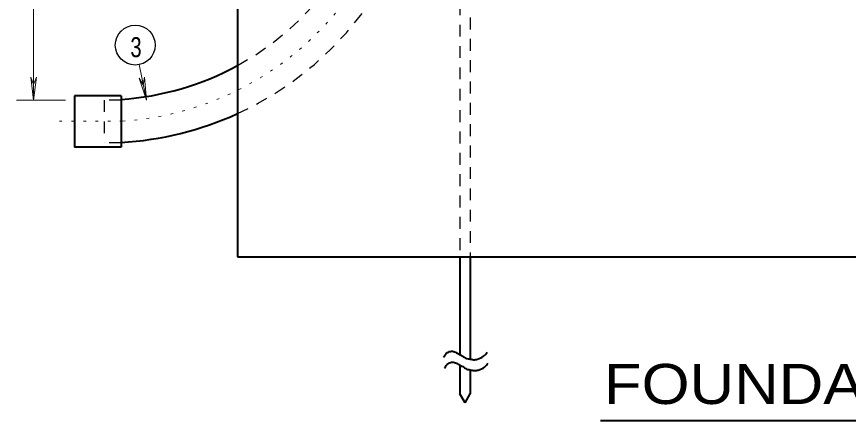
# Model space of a CAD drawing. Extents: x 312583 to 312854, y 144419 to 144597.
# Drawn here: x 312769.66 to 312801.16, y 144515.02 to 144530.33 of the extents above; entities that cross this region are included whole.
import ezdxf
from ezdxf.enums import TextEntityAlignment as Align

# ---------------------------------------------------------------- set-up
doc = ezdxf.new("R2010")
doc.units = 0
doc.header["$LTSCALE"] = 0.3
doc.linetypes.add('DOTTED', pattern=[1.5, 0.3, -1.2])
doc.linetypes.add('SHORT_DASHED', pattern=[2.7, 1.5, -1.2])
doc.layers.add('1', color=7, linetype='Continuous', lineweight=25)
doc.layers.add('2', color=7, linetype='Continuous', lineweight=13)

msp = doc.modelspace()

# ---------------------------------------------------------------- linework, layer by layer
at = {"layer": '1', "lineweight": 40}
for p, q in [((312778.0166, 144543.5879), (312778.0166, 144521.2243)), ((312773.616, 144527.3269), (312771.8526, 144527.3269)), ((312771.8526, 144527.3269), (312771.8526, 144525.3796)), ((312773.616, 144527.3269), (312773.616, 144525.3796)), ((312773.616, 144525.3796), (312771.8526, 144525.3796)), ((312778.0166, 144521.2243), (312840.6303, 144521.2243)), ((312786.4423, 144521.2243), (312786.4423, 144517.5136)), ((312786.841, 144521.2243), (312786.841, 144517.3449)), ((312786.4423, 144517.1149), (312786.4423, 144516.0263)), ((312786.841, 144516.9386), (312786.841, 144516.0263)), ((312786.6416, 144515.6813), (312786.4423, 144516.0263)), ((312786.6416, 144515.6813), (312786.841, 144516.0263))]:
    msp.add_line(p, q, dxfattribs=at)
at = {"layer": '1', "linetype": 'SHORT_DASHED'}
for p, q in [((312786.4423, 144534.0736), (312786.4423, 144521.2243)), ((312786.841, 144533.5369), (312786.841, 144521.2243)), ((312772.972, 144527.1659), (312772.972, 144525.5406)), ((312773.616, 144527.1659), (312772.972, 144527.1659)), ((312773.616, 144525.5406), (312772.972, 144525.5406))]:
    msp.add_line(p, q, dxfattribs=at)
at = {"layer": '1', "linetype": 'DOTTED', "lineweight": 13}
msp.add_line((312773.6696, 144526.3609), (312771.2776, 144526.3609), dxfattribs=at)
at = {"layer": '1', "linetype": 'SHORT_DASHED'}
for radius, start, end in [(10.6854, 298.57546, 1.79804), (12.3146, 294.52268, 358.54105)]:
    msp.add_arc((312772.9074, 144537.8539), radius, start, end, dxfattribs=at)
at = {"layer": '1', "linetype": 'DOTTED', "lineweight": 13}
msp.add_arc((312772.9074, 144537.8539), 11.516, 273.78468, 358.54081, dxfattribs=at)
at = {"layer": '1', "lineweight": 40}
for radius, start, end in [(10.6854, 273.78479, 298.57546), (12.3146, 273.28349, 294.52268)]:
    msp.add_arc((312772.9074, 144537.8539), radius, start, end, dxfattribs=at)
for points in [[(312785.829, 144517.4139), (312785.9746, 144517.5903), (312786.128, 144517.6439), (312786.2813, 144517.6056), (312786.4116, 144517.5289), (312786.5573, 144517.4523), (312786.6723, 144517.3833), (312786.841, 144517.3449), (312786.9713, 144517.3219), (312787.1093, 144517.3449), (312787.347, 144517.4523), (312787.485, 144517.6056)], [(312785.8673, 144517.0076), (312786.013, 144517.1763), (312786.1663, 144517.2299), (312786.3196, 144517.1916), (312786.45, 144517.1149), (312786.5956, 144517.0383), (312786.7106, 144516.9693), (312786.8793, 144516.9309), (312787.0096, 144516.9079), (312787.14, 144516.9309), (312787.3853, 144517.0383), (312787.5156, 144517.1916)]]:
    msp.add_spline(points, degree=3, dxfattribs=at)
at = {"layer": '2'}
for p, q in [((312774.2983, 144528.5076), (312774.5743, 144527.1659)), ((312770.1905, 144528.0323), (312770.2979, 144527.7563)), ((312770.2979, 144527.1659), (312770.1905, 144528.0323)), ((312770.4052, 144528.0323), (312770.2979, 144527.7563)), ((312770.2979, 144527.1659), (312770.4052, 144528.0323)), ((312774.2983, 144527.9939), (312774.4516, 144527.7486)), ((312774.5743, 144527.1659), (312774.2983, 144527.9939)), ((312774.5053, 144528.0399), (312774.4516, 144527.7486)), ((312774.5743, 144527.1659), (312774.5053, 144528.0399)), ((312771.5076, 144527.1659), (312769.6563, 144527.1659))]:
    msp.add_line(p, q, dxfattribs=at)
at = {"layer": '2', "lineweight": 40}
msp.add_line((312791.7706, 144515.0219), (312823.5413, 144515.0219), dxfattribs=at)
at = {"layer": '2'}
msp.add_lwpolyline([(312770.2979, 144527.1659), (312770.2979, 144542.3076), (312770.2979, 144544.2243)], dxfattribs=at)
at = {"layer": '2', "lineweight": 25}
msp.add_circle((312774.1507, 144529.2481), 0.7557, dxfattribs=at)

# ---------------------------------------------------------------- texts
at = {"layer": '2', "width": 0.75}
msp.add_text('3', height=0.76, dxfattribs=at).set_placement((312773.966, 144528.7904))
at = {"layer": '2', "width": 1.15}
msp.add_text('FOUNDATION TYPE "2M-MC"', height=1.52, dxfattribs=at).set_placement((312807.9907, 144515.6429), align=Align.CENTER)

doc.saveas('drawing.dxf')
